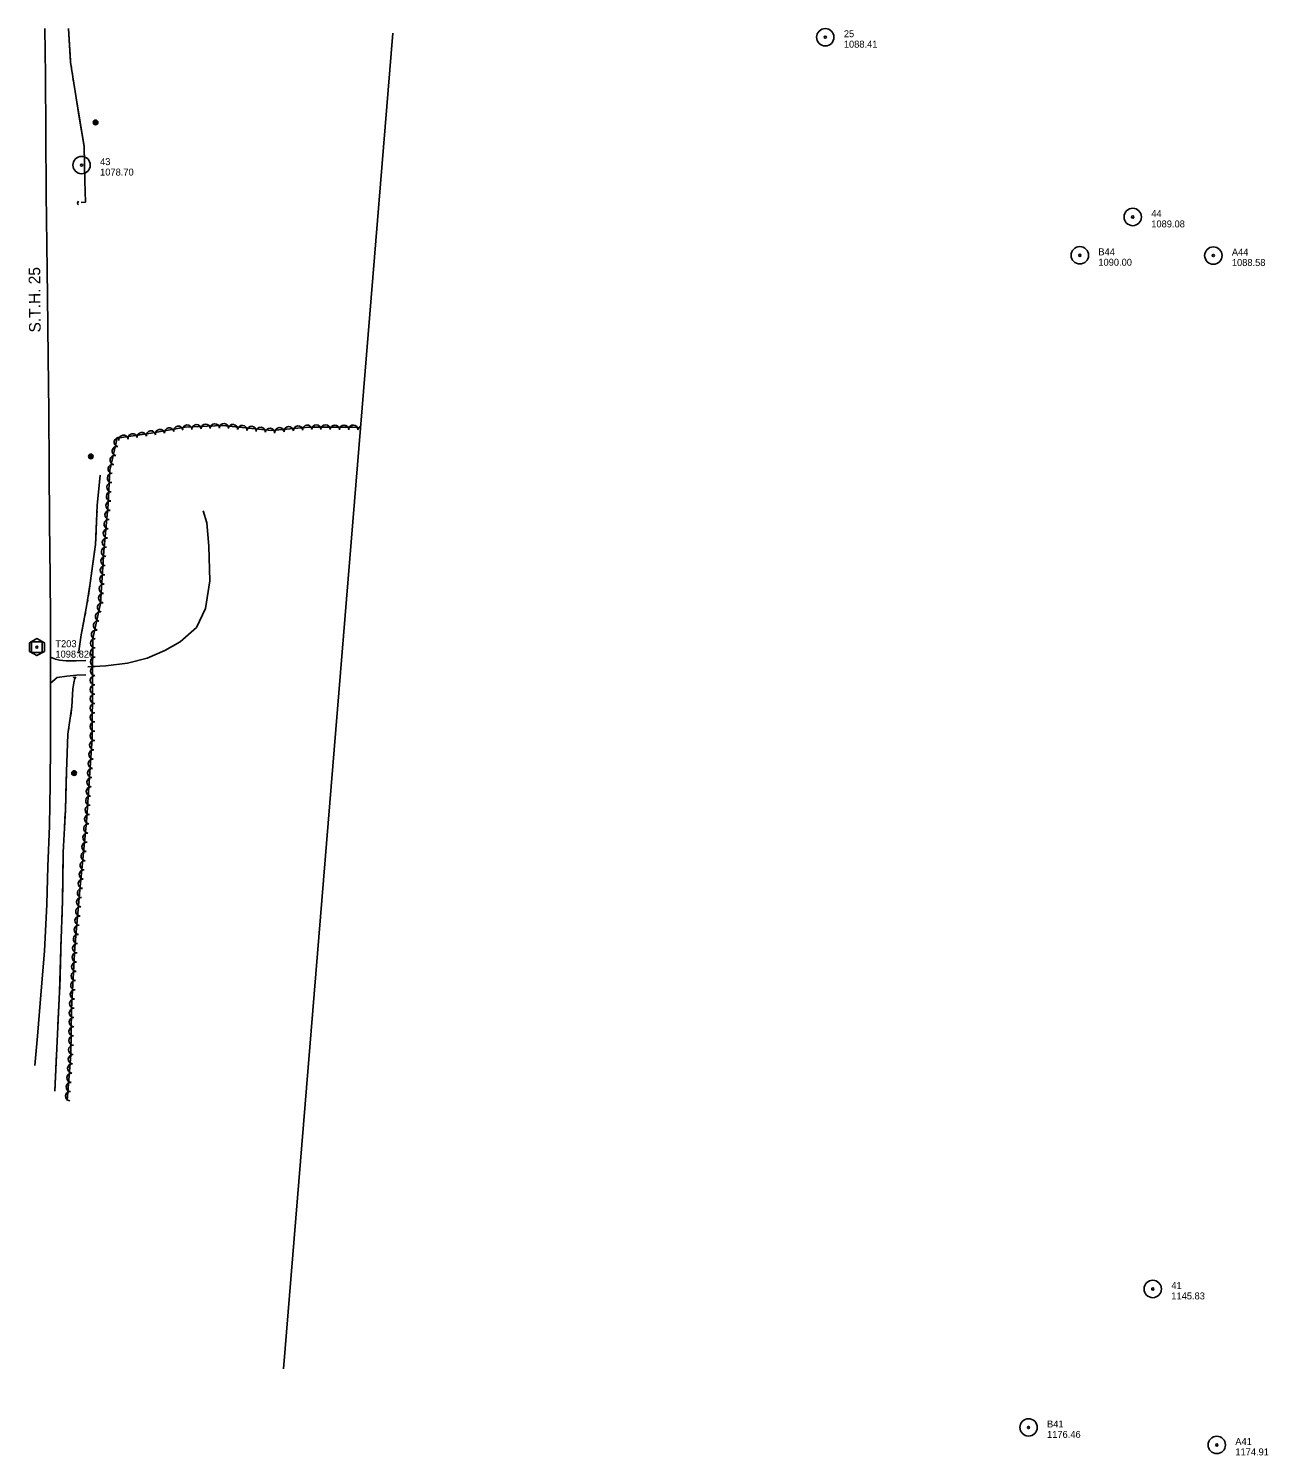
# Model space of a CAD drawing. Extents: x 296462 to 298813, y 30517 to 31770.
# Drawn here: x 297742 to 298813, y 30517 to 31750 of the extents above; entities that cross this region are included whole.
import ezdxf

# ---------------------------------------------------------------- set-up
doc = ezdxf.new("R2010")
doc.units = 0
for name, color, linetype in [('Level 11', 7, 'Continuous'), ('Level 14', 7, 'Continuous'), ('Level 15', 7, 'Continuous'), ('Level 17', 7, 'Continuous'), ('Level 18', 7, 'Continuous'), ('Level 19', 7, 'Continuous'), ('Level 4', 7, 'Continuous'), ('Level 5', 7, 'Continuous'), ('Level 6', 7, 'Continuous')]:
    doc.layers.add(name, color=color, linetype=linetype)

msp = doc.modelspace()

# ---------------------------------------------------------------- linework, layer by layer
at = {"layer": 'Level 11'}
msp.add_lwpolyline([(297747.7, 30854.1), (297750.1, 30879.6), (297753.4, 30918.6), (297756.2, 30952.9), (297758.1, 30993.6), (297759.2, 31026.1), (297760.4, 31061.2), (297761.1, 31097.3), (297761.5, 31131.9), (297761.5, 31168.3), (297761.5, 31203.7), (297761.3, 31240.3), (297761, 31275.6), (297760.6, 31323.1), (297760.2, 31370.6), (297759.8, 31419.2), (297759.3, 31465.9), (297758.9, 31518.7), (297758.3, 31563.4), (297757.7, 31607.1), (297757.4, 31659.6), (297757, 31709.7), (297756.5, 31749.8)], dxfattribs=at)
at = {"layer": 'Level 14'}
for centre, radius in [((297800.3, 31668.8), 2.02), ((297800.3, 31668.8), 1.52), ((297800.4, 31668.8), 1.01), ((297800.4, 31668.8), 0.502), ((297796.2, 31380.3), 2.02), ((297796.2, 31380.3), 1.52), ((297796.3, 31380.3), 1.01), ((297796.2, 31380.3), 0.502), ((297781.8, 31106.8), 2.02), ((297781.8, 31106.8), 1.52), ((297781.8, 31106.8), 1.01), ((297781.8, 31106.8), 0.502)]:
    msp.add_circle(centre, radius, dxfattribs=at)
at = {"layer": 'Level 15'}
for centre, radius, start, end in [((297786.7, 31599.2), 1.96, 127.941, 234.1806), ((297785.7, 31212.3), 1.51, 216.6186, 322.8581), ((297782.4, 31187.9), 1.58, 38.1963, 144.4359)]:
    msp.add_arc(centre, radius, start, end, dxfattribs=at)
at = {"layer": 'Level 17'}
for points in [[(297793.7, 31198.5), (297809.3, 31199.5), (297827.9, 31201.8), (297844.8, 31205.9), (297860.2, 31212.7), (297873.3, 31220.1), (297887.4, 31232.5), (297895.2, 31249), (297899.1, 31272.7), (297898.2, 31302.7), (297896.5, 31323), (297893.2, 31333.2)], [(297791.8, 31203.9), (297783.4, 31203.6), (297774.8, 31203.8), (297769.2, 31204.3), (297765.7, 31205.1), (297764.2, 31205.8), (297761.5, 31207)], [(297761.5, 31184.4), (297767.2, 31189.3), (297775.5, 31190.5), (297784, 31191.3), (297791.9, 31191.7)]]:
    msp.add_lwpolyline(points, dxfattribs=at)
at = {"layer": 'Level 18'}
msp.add_lwpolyline([(298029, 31405.1), (298022.7, 31405.5), (297984.6, 31405.6), (297952.3, 31402.7), (297910, 31406.9), (297877.6, 31405.5), (297848.4, 31400.5), (297819, 31396), (297812.7, 31368.4), (297811.2, 31338.9), (297807.3, 31298.5), (297804.5, 31253.3), (297797.8, 31222.9), (297797.6, 31187.1), (297797.5, 31136.8), (297795, 31102.9), (297792.5, 31064.5), (297786.7, 31005.7), (297782.4, 30956.1), (297779.6, 30902.8), (297778.9, 30863.4), (297775.9, 30823.8)], dxfattribs=at)
for centre, start, end in [((297871.8, 31402.4), 9.62, 189.6047), ((297879.4, 31403.5), 2.5603, 182.5449), ((297887.4, 31403.8), 2.5603, 182.5449), ((297895.4, 31404.2), 2.5603, 182.5449), ((297903.4, 31404.5), 2.5603, 182.5449), ((297911.1, 31404.7), 354.3162, 174.3009), ((297919, 31403.9), 354.3162, 174.3009), ((297927, 31403.1), 354.3162, 174.3009), ((297934.9, 31402.3), 354.3162, 174.3009), ((297975.2, 31402.7), 5.2008, 185.1855), ((297983.1, 31403.4), 5.2008, 185.1855), ((297990.9, 31403.5), 359.7578, 179.7425), ((297998.9, 31403.5), 359.7578, 179.7425), ((298006.9, 31403.4), 359.7578, 179.7425), ((298014.9, 31403.4), 359.7578, 179.7425), ((298022.8, 31403.4), 356.6845, 176.6692), ((298030.8, 31402.9), 113.7479, 176.6692), ((297820.4, 31392.7), 77.2328, 257.2175), ((297824.4, 31394.7), 8.7525, 188.7372), ((297832.3, 31395.9), 8.7525, 188.7372), ((297840.2, 31397.1), 8.7525, 188.7372), ((297848.1, 31398.4), 8.7525, 188.7372), ((297856, 31399.7), 9.62, 189.6047), ((297863.9, 31401), 9.62, 189.6047), ((297942.9, 31401.5), 354.3162, 174.3009), ((297950.9, 31400.7), 354.3162, 174.3009), ((297959.2, 31401.2), 5.2008, 185.1855), ((297967.2, 31402), 5.2008, 185.1855), ((297818.6, 31384.9), 77.2328, 257.2175), ((297815.1, 31369.3), 77.2328, 257.2175), ((297816.8, 31377.1), 77.2328, 257.2175), ((297814, 31353.7), 86.9886, 266.9732), ((297814.5, 31361.7), 86.9886, 266.9732), ((297813.6, 31345.8), 86.9886, 266.9732), ((297812.4, 31329.7), 84.5228, 264.5075), ((297813.2, 31337.7), 84.5228, 264.5075), ((297811.6, 31321.8), 84.5228, 264.5075), ((297810.1, 31305.8), 84.5228, 264.5075), ((297810.9, 31313.8), 84.5228, 264.5075), ((297809.3, 31297.9), 86.4561, 266.4408), ((297808.4, 31282), 86.4561, 266.4408), ((297808.9, 31290), 86.4561, 266.4408), ((297807.9, 31274), 86.4561, 266.4408), ((297806.9, 31258), 86.4561, 266.4408), ((297807.4, 31266), 86.4561, 266.4408), ((297804.1, 31242), 77.6772, 257.6618), ((297805.9, 31249.8), 77.6772, 257.6618), ((297802.4, 31234.2), 77.6772, 257.6618), ((297799.9, 31218.9), 89.727, 269.7117), ((297800.7, 31226.4), 77.6772, 257.6618), ((297799.9, 31210.9), 89.727, 269.7117), ((297799.8, 31202.9), 89.727, 269.7117), ((297799.8, 31194.9), 89.727, 269.7117), ((297799.7, 31186.9), 89.788, 269.7727), ((297799.7, 31178.9), 89.788, 269.7727), ((297799.7, 31170.9), 89.788, 269.7727), ((297799.6, 31162.9), 89.788, 269.7727), ((297799.6, 31154.9), 89.788, 269.7727), ((297799.6, 31146.9), 89.788, 269.7727), ((297799.6, 31138.9), 89.788, 269.7727), ((297798.5, 31122.8), 85.8665, 265.8512), ((297799.1, 31130.8), 85.8665, 265.8512), ((297797.4, 31106.8), 85.8665, 265.8512), ((297798, 31114.8), 85.8665, 265.8512), ((297796.8, 31098.9), 86.3362, 266.3209), ((297795.8, 31082.9), 86.3362, 266.3209), ((297796.3, 31090.9), 86.3362, 266.3209), ((297795.3, 31074.9), 86.3362, 266.3209), ((297794.1, 31058.9), 84.3352, 264.3199), ((297794.8, 31067), 86.3362, 266.3209), ((297793.3, 31051), 84.3352, 264.3199), ((297791.7, 31035), 84.3352, 264.3199), ((297792.5, 31043), 84.3352, 264.3199), ((297790.9, 31027.1), 84.3352, 264.3199), ((297789.3, 31011.2), 84.3352, 264.3199), ((297790.1, 31019.1), 84.3352, 264.3199), ((297788.6, 31003.2), 85.0571, 265.0418), ((297787.2, 30987.3), 85.0571, 265.0418), ((297787.9, 30995.3), 85.0571, 265.0418), ((297785.8, 30971.4), 85.0571, 265.0418), ((297786.5, 30979.3), 85.0571, 265.0418), ((297785.1, 30963.4), 85.0571, 265.0418), ((297784, 30947.5), 86.99, 266.9747), ((297784.5, 30955.5), 86.99, 266.9747), ((297783.6, 30939.5), 86.99, 266.9747), ((297782.8, 30923.5), 86.99, 266.9747), ((297783.2, 30931.5), 86.99, 266.9747), ((297782.4, 30915.6), 86.99, 266.9747), ((297781.6, 30899.6), 88.959, 268.9436), ((297781.9, 30907.6), 86.99, 266.9747), ((297781.5, 30891.7), 88.959, 268.9436), ((297781.2, 30875.7), 88.959, 268.9436), ((297781.3, 30883.7), 88.959, 268.9436), ((297781, 30867.7), 88.959, 268.9436), ((297780.1, 30851.6), 85.7793, 265.7639), ((297780.7, 30859.6), 85.7793, 265.7639), ((297778.9, 30835.6), 85.7793, 265.7639), ((297779.5, 30843.6), 85.7793, 265.7639), ((297778.3, 30827.7), 85.7793, 265.7639)]:
    msp.add_arc(centre, 4, start, end, dxfattribs=at)
at = {"layer": 'Level 19'}
for points in [[(297777, 31749.8), (297778.7, 31720.7), (297783.4, 31689.9), (297790.4, 31648.1), (297791, 31618.3), (297791.5, 31599.9), (297788, 31599.5)], [(297777, 31749.8), (297778.6, 31721.9)], [(297779.1, 31718.1), (297779.4, 31716.2)], [(297780, 31712.3), (297780.3, 31710.4)], [(297780.8, 31706.6), (297781.1, 31704.7)], [(297781.7, 31700.9), (297783.4, 31689.9), (297786.2, 31673.3)], [(297786.2, 31673.3), (297790.4, 31648.1), (297790.5, 31645.7)], [(297790.5, 31641.8), (297790.6, 31639.9)], [(297790.6, 31636), (297790.7, 31634.1)], [(297790.8, 31630.2), (297790.8, 31628.3)], [(297790.9, 31624.4), (297791, 31618.3), (297791.5, 31599.9), (297788, 31599.5)], [(297785.8, 31212), (297788, 31226.2), (297792.6, 31250.6), (297795.7, 31270.8), (297800.2, 31304.3), (297801.8, 31338), (297804.2, 31364.1)], [(297801.8, 31336.4), (297801.8, 31338), (297804.2, 31364.1)], [(297801.5, 31330.7), (297801.6, 31332.6)], [(297800.9, 31319.2), (297801, 31321.1)], [(297801.2, 31324.9), (297801.3, 31326.8)], [(297798, 31287.7), (297800.2, 31304.3), (297800.8, 31315.3)], [(297794.1, 31260.2), (297795.7, 31270.8), (297798, 31287.7)], [(297792.3, 31248.8), (297792.6, 31250.6), (297792.6, 31250.7)], [(297793.2, 31254.5), (297793.5, 31256.4)], [(297785.8, 31212), (297788, 31226.2), (297790.5, 31239.4)], [(297791.2, 31243.2), (297791.6, 31245.1)], [(297765, 30831.9), (297767, 30875.2), (297769.2, 30917.9), (297770.2, 30955.2), (297771.8, 30996.7), (297772.4, 31038.5), (297774.2, 31074.6), (297775.1, 31107.9), (297776.4, 31140.5), (297779.9, 31164.4), (297780.8, 31179.4), (297781.6, 31184.7), (297782.4, 31188.6)], [(297778.8, 31156.6), (297779.9, 31164.4), (297780.8, 31179.4), (297781.6, 31184.7), (297782.4, 31188.6)], [(297777.8, 31150), (297778.1, 31152.2)], [(297776.2, 31136.7), (297776.3, 31138.9)], [(297776.8, 31143.4), (297777.1, 31145.6)], [(297774.8, 31099.9), (297775.1, 31107.9), (297776, 31132.2)], [(297773.8, 31067.5), (297774.2, 31074.6), (297774.8, 31099.9)], [(297773.5, 31060.8), (297773.6, 31063)], [(297772.8, 31047.4), (297772.9, 31049.6)], [(297773.2, 31054.1), (297773.3, 31056.3)], [(297772, 31010.5), (297772.4, 31038.5), (297772.6, 31042.9)], [(297771.1, 30978.1), (297771.8, 30996.7), (297772, 31010.5)], [(297770.6, 30964.7), (297770.7, 30967)], [(297770.9, 30971.4), (297770.9, 30973.7)], [(297769.3, 30921.2), (297770.2, 30953.6)], [(297770.4, 30958), (297770.4, 30960.3)], [(297767.7, 30888.8), (297769.2, 30917.9), (297769.3, 30921.2)], [(297767, 30875.4), (297767.2, 30877.6)], [(297767.4, 30882.1), (297767.5, 30884.3)], [(297765, 30831.9), (297766.5, 30864.2)], [(297766.7, 30868.7), (297766.8, 30870.9)]]:
    msp.add_lwpolyline(points, dxfattribs=at)
at = {"layer": 'Level 4'}
msp.add_lwpolyline([(297962.5, 30592.1), (298056.9, 31745.8)], dxfattribs=at)
at = {"layer": 'Level 5'}
for points in [[(297743.2, 31219.3), (297743.2, 31211.9), (297749.7, 31208.2), (297756.1, 31211.8), (297756.1, 31219.2), (297749.6, 31222.9)], [(297745.1, 31211), (297745.1, 31220), (297754.1, 31220), (297754.1, 31211)]]:
    msp.add_lwpolyline(points, close=True, dxfattribs=at)
msp.add_circle((297749.6, 31215.5), 0.871, dxfattribs=at)
at = {"layer": 'Level 6'}
for centre, radius in [((298430.5, 31742.4), 7.5), ((298430.5, 31742.4), 0.96), ((297788.2, 31631.9), 7.5), ((297788.2, 31631.9), 0.96), ((298696, 31587.1), 7.5), ((298696, 31587.1), 0.96), ((298650.3, 31554), 7.5), ((298650.3, 31554), 0.96), ((298765.6, 31553.8), 7.5), ((298765.6, 31553.8), 0.96), ((298713.3, 30661.1), 7.5), ((298713.3, 30661.1), 0.96), ((298606, 30541.5), 7.5), ((298606, 30541.5), 0.96), ((298768.6, 30526.4), 7.5), ((298768.6, 30526.4), 0.96)]:
    msp.add_circle(centre, radius, dxfattribs=at)

# ---------------------------------------------------------------- texts
at = {"layer": 'Level 11'}
msp.add_text('S.T.H. 25', height=10, rotation=90.4566, dxfattribs=at).set_placement((297752.9, 31487.4))
at = {"layer": 'Level 5'}
for s, p in [('T203', (297765.6, 31215.5)), ('1098.820', (297765.6, 31206.5))]:
    msp.add_text(s, height=6, dxfattribs=at).set_placement(p)
at = {"layer": 'Level 6'}
for s, p in [('25', (298446.5, 31742.4)), ('1088.41', (298446.5, 31733.4)), ('43', (297804.2, 31631.9)), ('1078.70', (297804.2, 31622.9)), ('44', (298712, 31587.1)), ('1089.08', (298712, 31578.1)), ('B44', (298666.3, 31554)), ('A44', (298781.6, 31553.8)), ('1090.00', (298666.3, 31545)), ('1088.58', (298781.6, 31544.8)), ('41', (298729.3, 30661.1)), ('1145.83', (298729.3, 30652.1)), ('B41', (298622, 30541.5)), ('1176.46', (298622, 30532.5)), ('A41', (298784.6, 30526.4)), ('1174.91', (298784.6, 30517.4))]:
    msp.add_text(s, height=6, dxfattribs=at).set_placement(p)

doc.saveas('drawing.dxf')
